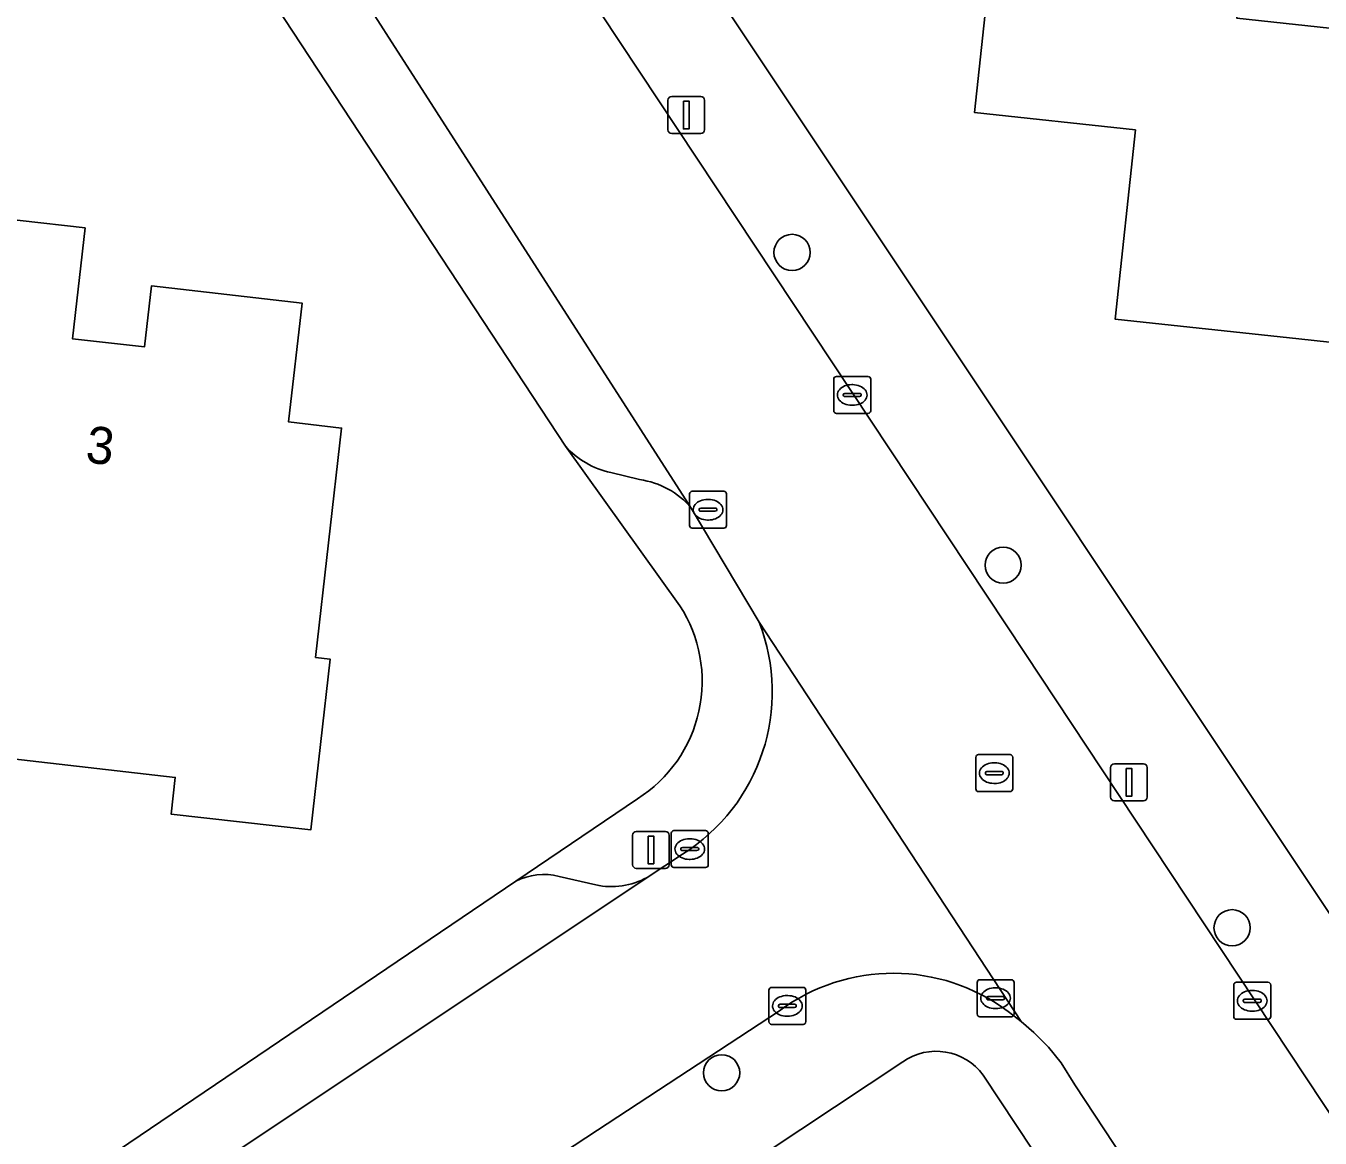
# Model space of a CAD drawing. Extents: x 162396 to 163643, y 386452 to 387406.
# Drawn here: x 163043.57 to 163078.58, y 386829.06 to 386859.14 of the extents above; entities that cross this region are included whole.
import ezdxf

# ---------------------------------------------------------------- set-up
doc = ezdxf.new("R2010")
doc.units = 0
for name, color, linetype in [('IMGEO_Boom', 7, 'Continuous'), ('IMGEO_Erf', 7, 'Continuous'), ('IMGEO_Kolk', 7, 'Continuous'), ('IMGEO_Lichtmast', 7, 'Continuous'), ('IMGEO_Pand', 7, 'Continuous'), ('IMGEO_Pand_nummerreeks', 7, 'Continuous'), ('IMGEO_Parkeervlak_open', 7, 'Continuous'), ('IMGEO_Rijbaan_lokaal_open', 7, 'Continuous'), ('IMGEO_Rioolput', 7, 'Continuous'), ('IMGEO_Voetpad_open', 7, 'Continuous')]:
    doc.layers.add(name, color=color, linetype=linetype)

msp = doc.modelspace()

# ---------------------------------------------------------------- linework, layer by layer
at = {"layer": 'IMGEO_Boom'}
for centre in [(163064.294, 386853.017), (163070.004, 386844.556), (163076.197, 386834.748), (163062.39, 386830.824)]:
    msp.add_circle(centre, 0.489, dxfattribs=at)
at = {"layer": 'IMGEO_Erf'}
for points in [[(163007.354, 386901.067), (163015.139, 386898.602), (163026.263, 386893.389), (163036.995, 386887.184), (163041.525, 386884.206), (163044.924, 386881.491), (163048.697, 386878.147), (163052.273, 386874.373), (163055.371, 386870.345), (163099.918, 386803.497)], [(163061.257, 386843.459), (163058.166, 386847.772), (163048.787, 386862.037), (163045.073, 386867.4)], [(163045.484, 386828.337), (163056.818, 386836.007), (163060.114, 386838.237)], [(163067.287, 386831.119), (163048.892, 386818.913)], [(163094.938, 386792.726), (163090.874, 386798.95), (163074.837, 386822.643), (163069.464, 386830.757)]]:
    msp.add_lwpolyline(points, dxfattribs=at)
for points in [[(163076.757, 386863.368), (163076.324, 386859.354), (163083.595, 386858.569), (163083.155, 386854.498), (163083.957, 386854.411), (163083.82, 386853.142), (163082.979, 386853.233), (163082.649, 386850.175), (163078.003, 386850.676), (163073.031, 386851.212), (163073.584, 386856.332), (163069.229, 386856.802), (163070.016, 386864.095), (163074.988, 386863.559)], [(163041.646, 386854.079), (163045.171, 386853.678), (163044.829, 386850.679), (163046.775, 386850.458), (163046.963, 386852.109), (163051.04, 386851.645), (163050.673, 386848.429), (163052.111, 386848.265), (163051.405, 386842.059), (163051.799, 386842.013), (163051.273, 386837.392), (163047.497, 386837.821), (163047.61, 386838.814), (163043.138, 386839.323), (163040.007, 386839.679), (163040.304, 386842.289)]]:
    msp.add_lwpolyline(points, close=True, dxfattribs=at)
for centre, radius, start, end in [((163058.104, 386841.413), 3.759, 302.3273, 32.9802), ((163068.192, 386829.834), 1.572, 35.9769, 125.1411)]:
    msp.add_arc(centre, radius, start, end, dxfattribs=at)
at = {"layer": 'IMGEO_Kolk'}
for p, q in [((163065.422, 386848.734), (163065.422, 386849.586)), ((163065.497, 386849.66), (163066.349, 386849.66)), ((163065.91, 386849.44), (163065.935, 386849.44)), ((163066.423, 386849.586), (163066.423, 386848.734)), ((163065.681, 386849.154), (163065.681, 386849.166)), ((163066.119, 386849.117), (163065.721, 386849.117)), ((163065.724, 386849.203), (163066.122, 386849.203)), ((163066.165, 386849.166), (163066.165, 386849.154)), ((163065.933, 386848.88), (163065.908, 386848.88)), ((163066.349, 386848.66), (163065.497, 386848.66)), ((163061.521, 386845.63), (163061.521, 386846.482)), ((163061.596, 386846.556), (163062.448, 386846.556)), ((163062.009, 386846.336), (163062.034, 386846.336)), ((163062.522, 386846.482), (163062.522, 386845.63)), ((163061.78, 386846.05), (163061.78, 386846.062)), ((163062.218, 386846.013), (163061.82, 386846.013)), ((163061.823, 386846.099), (163062.221, 386846.099)), ((163062.264, 386846.062), (163062.264, 386846.05)), ((163062.448, 386845.556), (163061.596, 386845.556)), ((163062.032, 386845.776), (163062.007, 386845.776)), ((163061.026, 386836.45), (163061.026, 386837.302)), ((163061.101, 386837.376), (163061.953, 386837.376)), ((163061.514, 386837.156), (163061.539, 386837.156)), ((163062.027, 386837.302), (163062.027, 386836.45)), ((163061.285, 386836.87), (163061.285, 386836.882)), ((163061.723, 386836.833), (163061.325, 386836.833)), ((163061.328, 386836.919), (163061.726, 386836.919)), ((163061.769, 386836.882), (163061.769, 386836.87)), ((163061.537, 386836.596), (163061.512, 386836.596)), ((163061.953, 386836.376), (163061.101, 386836.376)), ((163069.375, 386833.341), (163070.227, 386833.341)), ((163063.667, 386832.207), (163063.667, 386833.059)), ((163063.742, 386833.133), (163064.594, 386833.133)), ((163064.668, 386833.059), (163064.668, 386832.207)), ((163069.3, 386832.415), (163069.3, 386833.267)), ((163069.788, 386833.121), (163069.813, 386833.121)), ((163070.301, 386833.267), (163070.301, 386832.415)), ((163076.242, 386832.345), (163076.242, 386833.197)), ((163076.317, 386833.271), (163077.169, 386833.271)), ((163076.73, 386833.051), (163076.755, 386833.051)), ((163077.243, 386833.197), (163077.243, 386832.345)), ((163063.926, 386832.627), (163063.926, 386832.639)), ((163064.364, 386832.59), (163063.966, 386832.59)), ((163063.969, 386832.676), (163064.367, 386832.676)), ((163064.155, 386832.913), (163064.18, 386832.913)), ((163064.41, 386832.639), (163064.41, 386832.627)), ((163069.559, 386832.835), (163069.559, 386832.847)), ((163069.997, 386832.798), (163069.599, 386832.798)), ((163069.602, 386832.884), (163070, 386832.884)), ((163070.043, 386832.847), (163070.043, 386832.835)), ((163076.501, 386832.765), (163076.501, 386832.777)), ((163076.939, 386832.728), (163076.541, 386832.728)), ((163076.544, 386832.814), (163076.942, 386832.814)), ((163076.985, 386832.777), (163076.985, 386832.765)), ((163064.178, 386832.353), (163064.153, 386832.353)), ((163070.227, 386832.341), (163069.375, 386832.341)), ((163069.811, 386832.561), (163069.786, 386832.561)), ((163077.169, 386832.271), (163076.317, 386832.271)), ((163076.753, 386832.491), (163076.728, 386832.491)), ((163064.594, 386832.133), (163063.742, 386832.133))]:
    msp.add_line(p, q, dxfattribs=at)
for points in [[(163065.422, 386848.734), (163065.422, 386849.586)], [(163065.497, 386849.66), (163066.349, 386849.66)], [(163066.423, 386849.586), (163066.423, 386848.734)], [(163066.349, 386848.66), (163065.497, 386848.66)], [(163061.521, 386845.63), (163061.521, 386846.482)], [(163061.596, 386846.556), (163062.448, 386846.556)], [(163062.522, 386846.482), (163062.522, 386845.63)], [(163062.448, 386845.556), (163061.596, 386845.556)], [(163061.026, 386836.45), (163061.026, 386837.302)], [(163061.101, 386837.376), (163061.953, 386837.376)], [(163062.027, 386837.302), (163062.027, 386836.45)], [(163061.953, 386836.376), (163061.101, 386836.376)], [(163069.375, 386833.341), (163070.227, 386833.341)], [(163063.667, 386832.207), (163063.667, 386833.059)], [(163063.742, 386833.133), (163064.594, 386833.133)], [(163064.668, 386833.059), (163064.668, 386832.207)], [(163069.3, 386832.415), (163069.3, 386833.267)], [(163070.301, 386833.267), (163070.301, 386832.415)], [(163076.242, 386832.345), (163076.242, 386833.197)], [(163076.317, 386833.271), (163077.169, 386833.271)], [(163077.243, 386833.197), (163077.243, 386832.345)], [(163070.227, 386832.341), (163069.375, 386832.341)], [(163077.169, 386832.271), (163076.317, 386832.271)], [(163064.594, 386832.133), (163063.742, 386832.133)]]:
    msp.add_lwpolyline(points, dxfattribs=at)
for centre, radius, start, end in [((163065.499, 386849.584), 0.0765, 91.552, 178.448), ((163065.499, 386849.584), 0.0765, 91.552, 178.448), ((163066.347, 386849.584), 0.0765, 1.552, 88.448), ((163066.347, 386849.584), 0.0765, 1.552, 88.448), ((163065.721, 386849.163), 0.0403, 85.8775, 175.7526), ((163065.718, 386849.153), 0.0366, 178.938, 274.7102), ((163066.122, 386849.16), 0.043, 264.8664, 352.4533), ((163066.126, 386849.165), 0.0386, 1.7309, 96.639), ((163065.499, 386848.736), 0.0765, 181.552, 268.448), ((163065.499, 386848.736), 0.0765, 181.552, 268.448), ((163066.347, 386848.736), 0.0765, 271.552, 358.448), ((163066.347, 386848.736), 0.0765, 271.552, 358.448), ((163061.598, 386846.48), 0.0765, 91.552, 178.448), ((163061.598, 386846.48), 0.0765, 91.552, 178.448), ((163062.446, 386846.48), 0.0765, 1.552, 88.448), ((163062.446, 386846.48), 0.0765, 1.552, 88.448), ((163061.82, 386846.059), 0.0403, 85.8775, 175.7526), ((163061.817, 386846.049), 0.0366, 178.938, 274.7102), ((163062.221, 386846.056), 0.043, 264.8664, 352.4533), ((163062.225, 386846.061), 0.0386, 1.7309, 96.639), ((163061.598, 386845.632), 0.0765, 181.552, 268.448), ((163061.598, 386845.632), 0.0765, 181.552, 268.448), ((163062.446, 386845.632), 0.0765, 271.552, 358.448), ((163062.446, 386845.632), 0.0765, 271.552, 358.448), ((163061.103, 386837.3), 0.0765, 91.552, 178.448), ((163061.103, 386837.3), 0.0765, 91.552, 178.448), ((163061.951, 386837.3), 0.0765, 1.552, 88.448), ((163061.951, 386837.3), 0.0765, 1.552, 88.448), ((163061.325, 386836.879), 0.0403, 85.8775, 175.7526), ((163061.322, 386836.869), 0.0366, 178.938, 274.7102), ((163061.726, 386836.876), 0.043, 264.8664, 352.4533), ((163061.73, 386836.881), 0.0386, 1.7309, 96.639), ((163061.103, 386836.452), 0.0765, 181.552, 268.448), ((163061.103, 386836.452), 0.0765, 181.552, 268.448), ((163061.951, 386836.452), 0.0765, 271.552, 358.448), ((163061.951, 386836.452), 0.0765, 271.552, 358.448), ((163069.377, 386833.265), 0.0765, 91.552, 178.448), ((163069.377, 386833.265), 0.0765, 91.552, 178.448), ((163070.225, 386833.265), 0.0765, 1.552, 88.448), ((163070.225, 386833.265), 0.0765, 1.552, 88.448), ((163063.744, 386833.057), 0.0765, 91.552, 178.448), ((163063.744, 386833.057), 0.0765, 91.552, 178.448), ((163064.592, 386833.057), 0.0765, 1.552, 88.448), ((163064.592, 386833.057), 0.0765, 1.552, 88.448), ((163076.319, 386833.195), 0.0765, 91.552, 178.448), ((163076.319, 386833.195), 0.0765, 91.552, 178.448), ((163077.167, 386833.195), 0.0765, 1.552, 88.448), ((163077.167, 386833.195), 0.0765, 1.552, 88.448), ((163063.966, 386832.636), 0.0403, 85.8775, 175.7526), ((163063.963, 386832.626), 0.0366, 178.938, 274.7102), ((163064.367, 386832.633), 0.043, 264.8664, 352.4533), ((163064.371, 386832.638), 0.0386, 1.7309, 96.639), ((163069.599, 386832.844), 0.0403, 85.8775, 175.7526), ((163069.596, 386832.834), 0.0366, 178.938, 274.7102), ((163070, 386832.841), 0.043, 264.8664, 352.4533), ((163070.004, 386832.846), 0.0386, 1.7309, 96.639), ((163076.541, 386832.774), 0.0403, 85.8775, 175.7526), ((163076.538, 386832.764), 0.0366, 178.938, 274.7102), ((163076.942, 386832.771), 0.043, 264.8664, 352.4533), ((163076.946, 386832.776), 0.0386, 1.7309, 96.639), ((163069.377, 386832.417), 0.0765, 181.552, 268.448), ((163069.377, 386832.417), 0.0765, 181.552, 268.448), ((163070.225, 386832.417), 0.0765, 271.552, 358.448), ((163070.225, 386832.417), 0.0765, 271.552, 358.448), ((163076.319, 386832.347), 0.0765, 181.552, 268.448), ((163076.319, 386832.347), 0.0765, 181.552, 268.448), ((163077.167, 386832.347), 0.0765, 271.552, 358.448), ((163077.167, 386832.347), 0.0765, 271.552, 358.448), ((163063.744, 386832.209), 0.0765, 181.552, 268.448), ((163063.744, 386832.209), 0.0765, 181.552, 268.448), ((163064.592, 386832.209), 0.0765, 271.552, 358.448), ((163064.592, 386832.209), 0.0765, 271.552, 358.448)]:
    msp.add_arc(centre, radius, start, end, dxfattribs=at)
for centre, major_axis, ratio, start_param, end_param in [((163065.909, 386849.16), (-0.387, 0.002), 0.722429, 4.712389, 7.853982), ((163065.934, 386849.16), (-0.39, 0.002), 0.717154, 1.570796, 4.712389), ((163062.008, 386846.056), (-0.387, 0.002), 0.722429, 4.712389, 7.853982), ((163062.033, 386846.056), (-0.39, 0.002), 0.717154, 1.570796, 4.712389), ((163061.513, 386836.876), (-0.387, 0.002), 0.722429, 4.712389, 7.853982), ((163061.538, 386836.876), (-0.39, 0.002), 0.717154, 1.570796, 4.712389), ((163069.787, 386832.841), (-0.387, 0.002), 0.722429, 4.712389, 7.853982), ((163069.812, 386832.841), (-0.39, 0.002), 0.717154, 1.570796, 4.712389), ((163076.729, 386832.771), (-0.387, 0.002), 0.722429, 4.712389, 7.853982), ((163076.754, 386832.771), (-0.39, 0.002), 0.717154, 1.570796, 4.712389), ((163064.154, 386832.633), (-0.387, 0.002), 0.722429, 4.712389, 7.853982), ((163064.179, 386832.633), (-0.39, 0.002), 0.717154, 1.570796, 4.712389)]:
    msp.add_ellipse(centre, major_axis=major_axis, ratio=ratio, start_param=start_param, end_param=end_param, dxfattribs=at)
at = {"layer": 'IMGEO_Lichtmast'}
for p, q in [((163060.938, 386856.334), (163060.938, 386857.134)), ((163060.938, 386857.134), (163060.938, 386856.334)), ((163061.038, 386857.234), (163061.828, 386857.234)), ((163061.828, 386857.234), (163061.038, 386857.234)), ((163061.928, 386857.134), (163061.928, 386856.334)), ((163061.928, 386856.334), (163061.928, 386857.134)), ((163061.828, 386856.234), (163061.038, 386856.234)), ((163061.038, 386856.234), (163061.828, 386856.234)), ((163072.913, 386838.281), (163072.913, 386839.081)), ((163072.913, 386839.081), (163072.913, 386838.281)), ((163073.013, 386839.181), (163073.803, 386839.181)), ((163073.803, 386839.181), (163073.013, 386839.181)), ((163073.903, 386839.081), (163073.903, 386838.281)), ((163073.903, 386838.281), (163073.903, 386839.081)), ((163073.803, 386838.181), (163073.013, 386838.181)), ((163073.013, 386838.181), (163073.803, 386838.181)), ((163059.982, 386836.453), (163059.982, 386837.253)), ((163059.982, 386837.253), (163059.982, 386836.453)), ((163060.082, 386837.353), (163060.872, 386837.353)), ((163060.872, 386837.353), (163060.082, 386837.353)), ((163060.972, 386837.253), (163060.972, 386836.453)), ((163060.972, 386836.453), (163060.972, 386837.253)), ((163060.872, 386836.353), (163060.082, 386836.353)), ((163060.082, 386836.353), (163060.872, 386836.353))]:
    msp.add_line(p, q, dxfattribs=at)
for points in [[(163061.358, 386857.109), (163061.508, 386857.109), (163061.508, 386856.359), (163061.358, 386856.359), (163061.358, 386857.109)], [(163073.333, 386839.056), (163073.483, 386839.056), (163073.483, 386838.306), (163073.333, 386838.306), (163073.333, 386839.056)], [(163060.402, 386837.228), (163060.552, 386837.228), (163060.552, 386836.478), (163060.402, 386836.478), (163060.402, 386837.228)]]:
    msp.add_lwpolyline(points, dxfattribs=at)
for centre, start, end in [((163061.038, 386857.134), 90, 180), ((163061.038, 386857.134), 90, 180), ((163061.828, 386857.134), 0, 90), ((163061.828, 386857.134), 360, 90), ((163061.038, 386856.334), 180, 270), ((163061.038, 386856.334), 180, 270), ((163061.828, 386856.334), 270, 0), ((163061.828, 386856.334), 270, 0), ((163073.013, 386839.081), 90, 180), ((163073.013, 386839.081), 90, 180), ((163073.803, 386839.081), 0, 90), ((163073.803, 386839.081), 360, 90), ((163073.013, 386838.281), 180, 270), ((163073.013, 386838.281), 180, 270), ((163073.803, 386838.281), 270, 0), ((163073.803, 386838.281), 270, 0), ((163060.082, 386837.253), 90, 180), ((163060.082, 386837.253), 90, 180), ((163060.872, 386837.253), 0, 90), ((163060.872, 386837.253), 360, 90), ((163060.082, 386836.453), 180, 270), ((163060.082, 386836.453), 180, 270), ((163060.872, 386836.453), 270, 0), ((163060.872, 386836.453), 270, 0)]:
    msp.add_arc(centre, 0.1, start, end, dxfattribs=at)
at = {"layer": 'IMGEO_Pand'}
for points in [[(163074.988, 386863.559), (163070.016, 386864.095), (163069.229, 386856.802), (163073.584, 386856.332), (163073.031, 386851.212), (163078.003, 386850.676), (163082.649, 386850.175), (163082.979, 386853.233), (163083.82, 386853.142), (163083.957, 386854.411), (163083.155, 386854.498), (163083.595, 386858.569), (163076.324, 386859.354), (163076.757, 386863.368)], [(163052.111, 386848.265), (163050.673, 386848.429), (163051.04, 386851.645), (163046.963, 386852.109), (163046.775, 386850.458), (163044.829, 386850.679), (163045.171, 386853.678), (163041.646, 386854.079), (163040.304, 386842.289), (163040.007, 386839.679), (163043.138, 386839.323), (163047.61, 386838.814), (163047.497, 386837.821), (163051.273, 386837.392), (163051.799, 386842.013), (163051.405, 386842.059)]]:
    msp.add_lwpolyline(points, close=True, dxfattribs=at)
at = {"layer": 'IMGEO_Parkeervlak_open'}
for points in [[(162957.384, 386901.072), (162973.038, 386898.121), (163000, 386892.581), (163004.674, 386891.621), (163011.909, 386889.211), (163018.861, 386886), (163024.953, 386882.723), (163030.394, 386879.532), (163035.617, 386876.218), (163040.482, 386872.453), (163045.073, 386867.4), (163048.787, 386862.037), (163058.166, 386847.772)], [(163061.569, 386846.098), (163050.515, 386863.314)], [(163059.391, 386847.06), (163060.17, 386846.87)], [(163046.355, 386826.754), (163060.375, 386836.109)], [(163058.984, 386835.906), (163057.992, 386836.138)], [(163056.818, 386836.007), (163045.484, 386828.337)]]:
    msp.add_lwpolyline(points, dxfattribs=at)
for centre, radius, start, end in [((163059.897, 386849.34), 2.336, 222.1784, 257.4892), ((163059.871, 386844.674), 2.216, 39.9794, 82.2388), ((163057.58, 386834.508), 1.681, 75.7978, 116.9361), ((163059.41, 386837.856), 1.996, 257.6852, 298.9209)]:
    msp.add_arc(centre, radius, start, end, dxfattribs=at)
at = {"layer": 'IMGEO_Rijbaan_lokaal_open'}
for points in [[(163084.661, 386820.941), (163072.682, 386839.022), (163070.601, 386842.162), (163058.066, 386861.082), (163055.939, 386864.293), (163054.925, 386865.823), (163051.94, 386869.963), (163048.719, 386873.794), (163045.549, 386876.981)], [(163050.515, 386863.314), (163061.569, 386846.098), (163063.403, 386843.018), (163070.493, 386832.212), (163070.836, 386831.917), (163071.232, 386831.515), (163071.575, 386831.097), (163071.948, 386830.5), (163073.268, 386828.487)], [(163070.137, 386832.483), (163070.493, 386832.212), (163063.403, 386843.018)], [(163061.331, 386836.738), (163060.375, 386836.109), (163046.355, 386826.754)], [(163046.696, 386821.167), (163047.956, 386821.995), (163052.249, 386824.813), (163055.219, 386826.764), (163059.032, 386829.268), (163063.954, 386832.5)]]:
    msp.add_lwpolyline(points, dxfattribs=at)
for centre, radius, start, end in [((163058.578, 386841.128), 5.182, 302.093, 21.3878), ((163067.034, 386828.346), 5.171, 53.1277, 126.5572)]:
    msp.add_arc(centre, radius, start, end, dxfattribs=at)
at = {"layer": 'IMGEO_Rioolput'}
for p, q in [((163069.265, 386838.505), (163069.265, 386839.357)), ((163069.34, 386839.431), (163070.192, 386839.431)), ((163070.266, 386839.357), (163070.266, 386838.505)), ((163069.524, 386838.925), (163069.524, 386838.937)), ((163069.962, 386838.888), (163069.564, 386838.888)), ((163069.567, 386838.974), (163069.965, 386838.974)), ((163069.753, 386839.211), (163069.778, 386839.211)), ((163070.008, 386838.937), (163070.008, 386838.925)), ((163069.776, 386838.651), (163069.751, 386838.651)), ((163070.192, 386838.431), (163069.34, 386838.431))]:
    msp.add_line(p, q, dxfattribs=at)
for points in [[(163069.265, 386838.505), (163069.265, 386839.357)], [(163069.34, 386839.431), (163070.192, 386839.431)], [(163070.266, 386839.357), (163070.266, 386838.505)], [(163070.192, 386838.431), (163069.34, 386838.431)]]:
    msp.add_lwpolyline(points, dxfattribs=at)
for centre, radius, start, end in [((163069.342, 386839.355), 0.0765, 91.552, 178.448), ((163069.342, 386839.355), 0.0765, 91.552, 178.448), ((163070.19, 386839.355), 0.0765, 1.552, 88.448), ((163070.19, 386839.355), 0.0765, 1.552, 88.448), ((163069.564, 386838.934), 0.0403, 85.8775, 175.7526), ((163069.561, 386838.924), 0.0366, 178.938, 274.7102), ((163069.965, 386838.931), 0.043, 264.8664, 352.4533), ((163069.969, 386838.936), 0.0386, 1.7309, 96.639), ((163069.342, 386838.507), 0.0765, 181.552, 268.448), ((163069.342, 386838.507), 0.0765, 181.552, 268.448), ((163070.19, 386838.507), 0.0765, 271.552, 358.448), ((163070.19, 386838.507), 0.0765, 271.552, 358.448)]:
    msp.add_arc(centre, radius, start, end, dxfattribs=at)
for centre, major_axis, ratio, start_param, end_param in [((163069.752, 386838.931), (-0.387, 0.002), 0.722429, 4.712389, 7.853982), ((163069.777, 386838.931), (-0.39, 0.002), 0.717154, 1.570796, 4.712389)]:
    msp.add_ellipse(centre, major_axis=major_axis, ratio=ratio, start_param=start_param, end_param=end_param, dxfattribs=at)
at = {"layer": 'IMGEO_Voetpad_open'}
for points in [[(163099.918, 386803.497), (163055.371, 386870.345), (163052.273, 386874.373), (163048.697, 386878.147), (163044.924, 386881.491), (163041.525, 386884.206), (163036.995, 386887.184), (163026.263, 386893.389), (163015.139, 386898.602)], [(163045.549, 386876.981), (163048.719, 386873.794), (163051.94, 386869.963), (163054.925, 386865.823), (163055.939, 386864.293), (163058.066, 386861.082), (163070.601, 386842.162), (163072.682, 386839.022), (163084.661, 386820.941), (163086.459, 386818.227), (163088.943, 386814.478), (163089.654, 386813.404), (163097.59, 386801.208), (163098.684, 386799.487), (163098.774, 386799.346), (163099.704, 386798.039)], [(163058.166, 386847.772), (163061.257, 386843.459)], [(163060.17, 386846.87), (163059.391, 386847.06)], [(163063.403, 386843.018), (163061.569, 386846.098)], [(163060.114, 386838.237), (163056.818, 386836.007)], [(163060.375, 386836.109), (163061.331, 386836.738)], [(163057.992, 386836.138), (163058.984, 386835.906)], [(163063.954, 386832.5), (163059.032, 386829.268), (163055.219, 386826.764), (163052.249, 386824.813), (163047.956, 386821.995), (163046.696, 386821.167)], [(163074.36, 386826.913), (163073.268, 386828.487), (163071.948, 386830.5), (163071.575, 386831.097), (163071.232, 386831.515), (163070.836, 386831.917), (163070.493, 386832.212), (163070.137, 386832.483)], [(163048.892, 386818.913), (163067.287, 386831.119)], [(163069.464, 386830.757), (163074.837, 386822.643), (163074.86, 386822.707)]]:
    msp.add_lwpolyline(points, dxfattribs=at)
for centre, radius, start, end in [((163059.897, 386849.34), 2.336, 222.1784, 257.4892), ((163059.871, 386844.674), 2.216, 39.9794, 82.2388), ((163058.104, 386841.413), 3.759, 302.3273, 32.9802), ((163058.578, 386841.128), 5.182, 302.093, 21.3878), ((163057.58, 386834.508), 1.681, 75.7978, 116.9361), ((163059.41, 386837.856), 1.996, 257.6852, 298.9209), ((163067.034, 386828.346), 5.171, 53.1277, 126.5572), ((163068.192, 386829.834), 1.572, 35.9769, 125.1411)]:
    msp.add_arc(centre, radius, start, end, dxfattribs=at)

# ---------------------------------------------------------------- texts
at = {"layer": 'IMGEO_Pand_nummerreeks'}
msp.add_text('3', height=1, rotation=353.5198, dxfattribs=at).set_placement((163045.158, 386847.34))

doc.saveas('drawing.dxf')
